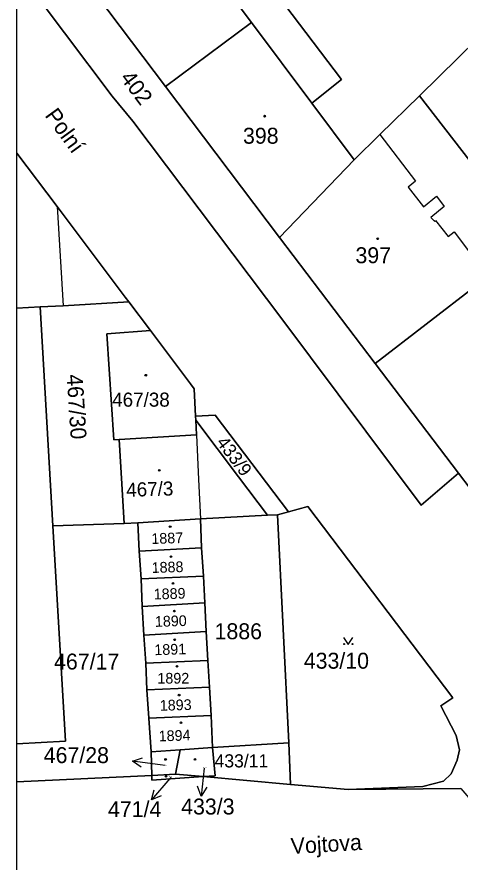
# Model space of a CAD drawing. Extents: x -598934 to -598196, y -1162208 to -1161502.
# Drawn here: x -598932 to -598884.8, y -1162016.6 to -1161926.4 of the extents above; entities that cross this region are included whole.
import ezdxf

# ---------------------------------------------------------------- set-up
doc = ezdxf.new("R2010")
doc.units = 0
for name, color, linetype in [('KN_CAR_KR', 7, 'Continuous'), ('KN_KULTURY', 7, 'Continuous'), ('KN_PARC_CIS_POM', 7, 'Continuous'), ('KN_PARC_CIS_POZ', 7, 'Continuous'), ('KN_PARC_CIS_STAV', 7, 'Continuous'), ('KN_PARC_PLOCHA', 7, 'Continuous'), ('KN_ULICE', 7, 'Continuous'), ('PARC_C_SIPKA', 7, 'Continuous'), ('parcely_l', 7, 'Continuous')]:
    doc.layers.add(name, color=color, linetype=linetype)

msp = doc.modelspace()

# ---------------------------------------------------------------- linework, layer by layer
at = {"layer": 'KN_CAR_KR'}
for points in [[(-598893.33, -1161938.99), (-598889.53, -1161943.97)], [(-598889.53, -1161943.97), (-598890.3, -1161944.59)], [(-598890.3, -1161944.59), (-598888.69, -1161946.7)], [(-598888.69, -1161946.7), (-598887.3, -1161945.55)], [(-598887.3, -1161945.55), (-598886.49, -1161946.67)], [(-598927.74, -1161946.65), (-598927.08, -1161957.24)], [(-598886.49, -1161946.67), (-598887.89, -1161947.84)], [(-598887.89, -1161947.84), (-598887.48, -1161948.25)], [(-598887.48, -1161948.25), (-598887.4, -1161948.17)], [(-598887.4, -1161948.17), (-598886.03, -1161949.88)], [(-598886.03, -1161949.88), (-598885.42, -1161949.38)], [(-598885.42, -1161949.38), (-598881.85, -1161954.09)], [(-598912.89, -1161971.03), (-598912.66, -1161975.76)], [(-598912.66, -1161975.76), (-598912.45, -1161979.98)]]:
    msp.add_lwpolyline(points, dxfattribs=at)
at = {"layer": 'KN_KULTURY'}
msp.add_lwpolyline([(-598897.192, -1161992.622), (-598896.692, -1161993.372), (-598896.192, -1161992.622)], dxfattribs=at)
for centre, radius in [((-598905.61, -1161937.03), 0.09), ((-598905.61, -1161937.03), 0.0398), ((-598893.56, -1161950.11), 0.09), ((-598893.56, -1161950.11), 0.0398), ((-598918.28, -1161964.66), 0.09), ((-598918.28, -1161964.66), 0.0398), ((-598916.84, -1161974.8), 0.09), ((-598916.84, -1161974.8), 0.0398), ((-598915.68, -1161980.81), 0.09), ((-598915.68, -1161980.81), 0.0398), ((-598915.59, -1161984), 0.09), ((-598915.59, -1161984), 0.0398), ((-598915.38, -1161986.86), 0.09), ((-598915.38, -1161986.86), 0.0398), ((-598915.23, -1161989.81), 0.09), ((-598915.23, -1161989.81), 0.0398), ((-598915.2, -1161992.87), 0.09), ((-598915.2, -1161992.87), 0.0398), ((-598897.142, -1161993.321), 0.05), ((-598896.243, -1161993.321), 0.05), ((-598914.95, -1161995.7), 0.09), ((-598914.95, -1161995.7), 0.0398), ((-598914.72, -1161998.77), 0.09), ((-598914.72, -1161998.77), 0.0398), ((-598914.53, -1162001.72), 0.09), ((-598914.53, -1162001.72), 0.0398), ((-598916.17, -1162005.63), 0.09), ((-598916.17, -1162005.63), 0.0398), ((-598913.04, -1162005.63), 0.09), ((-598913.04, -1162005.63), 0.0398), ((-598916.13, -1162007.43), 0.09), ((-598916.13, -1162007.43), 0.0398)]:
    msp.add_circle(centre, radius, dxfattribs=at)
at = {"layer": 'KN_PARC_PLOCHA'}
for points in [[(-598820.93, -1161992.32), (-598829.17, -1161992.77), (-598829.29, -1161990.1), (-598829.45, -1161986.79), (-598829.55, -1161985.5), (-598829.92, -1161978.95), (-598842.8, -1161965.85), (-598849.62, -1161958.8), (-598867.42, -1161940.58), (-598880.89, -1161926.8), (-598889.11, -1161934.86), (-598893.33, -1161938.99), (-598896.07, -1161941.68), (-598900.57, -1161935.66), (-598897.41, -1161933.11), (-598907.94, -1161919.22), (-598928.61, -1161891.58), (-598931.22, -1161882.34), (-598932.017, -1161880.677), (-598932.017, -1161860.81)], [(-598884.71, -1162008.72), (-598896.69, -1162008.84), (-598888.76, -1162008.53), (-598886.53, -1162007.94), (-598885.74, -1162007.17), (-598885.1, -1162005.69), (-598884.84, -1162004.62), (-598885.2, -1162003.07), (-598886.83, -1161999.9), (-598885.54, -1161999.06), (-598901.01, -1161978.64), (-598903.08, -1161979.22), (-598910.89, -1161968.92), (-598912.98, -1161969.02), (-598913.12, -1161966.09), (-598913.51, -1161965.57), (-598917.78, -1161959.89), (-598920.08, -1161956.84), (-598920.47, -1161956.32), (-598927.74, -1161946.65), (-598932.017, -1161940.968), (-598932.017, -1161921.366), (-598921.86, -1161934.91), (-598919.65, -1161937.58), (-598903.67, -1161958.78), (-598888.91, -1161978.52), (-598884.94, -1161975.11), (-598873.75, -1161989.83)]]:
    msp.add_lwpolyline(points, dxfattribs=at)
for points in [[(-598897.41, -1161933.11), (-598900.57, -1161935.66), (-598907.01, -1161927.05), (-598918.02, -1161912.34), (-598928.99, -1161897.67), (-598932.017, -1161893.629), (-598932.017, -1161880.677), (-598931.22, -1161882.34), (-598928.61, -1161891.58), (-598907.94, -1161919.22)], [(-598907.01, -1161927.05), (-598916.16, -1161933.87), (-598927.15, -1161919.28), (-598918.02, -1161912.34)], [(-598927.15, -1161919.28), (-598916.16, -1161933.87), (-598904.02, -1161949.98), (-598893.84, -1161963.41), (-598884.94, -1161975.11), (-598888.91, -1161978.52), (-598903.67, -1161958.78), (-598919.65, -1161937.58), (-598921.86, -1161934.91), (-598932.017, -1161921.366), (-598932.017, -1161912.818)], [(-598867.42, -1161940.58), (-598872.02, -1161944.33), (-598877.53, -1161949.83), (-598889.11, -1161934.86), (-598880.89, -1161926.8)], [(-598900.57, -1161935.66), (-598896.07, -1161941.68), (-598904.02, -1161949.98), (-598916.16, -1161933.87), (-598907.01, -1161927.05)], [(-598877.53, -1161949.83), (-598881.85, -1161954.09), (-598882.96, -1161955.02), (-598893.84, -1161963.41), (-598904.02, -1161949.98), (-598896.07, -1161941.68), (-598893.33, -1161938.99), (-598889.11, -1161934.86)], [(-598920.08, -1161956.84), (-598927.08, -1161957.24), (-598929.55, -1161957.38), (-598932.017, -1161957.521), (-598932.017, -1161940.968), (-598927.74, -1161946.65), (-598920.47, -1161956.32)], [(-598863.18, -1161981.51), (-598864.24, -1161982.22), (-598873.75, -1161989.83), (-598884.94, -1161975.11), (-598893.84, -1161963.41), (-598882.96, -1161955.02)], [(-598928.18, -1161980.72), (-598926.84, -1162003.67), (-598932.017, -1162003.962), (-598932.017, -1161957.521), (-598929.55, -1161957.38)], [(-598917.78, -1161959.89), (-598922.44, -1161960.25), (-598921.67, -1161971.54), (-598921.13, -1161971.51), (-598920.82, -1161976.25), (-598920.57, -1161980.46), (-598928.18, -1161980.72), (-598929.55, -1161957.38), (-598927.08, -1161957.24), (-598920.08, -1161956.84)], [(-598912.98, -1161969.02), (-598912.96, -1161969.44), (-598912.89, -1161971.03), (-598921.13, -1161971.51), (-598921.67, -1161971.54), (-598922.44, -1161960.25), (-598917.78, -1161959.89), (-598913.51, -1161965.57), (-598913.12, -1161966.09)], [(-598903.08, -1161979.22), (-598904.23, -1161979.56), (-598905.31, -1161979.57), (-598908.38, -1161975.5), (-598912.96, -1161969.44), (-598912.98, -1161969.02), (-598910.89, -1161968.92)], [(-598905.31, -1161979.57), (-598912.45, -1161979.98), (-598919.13, -1161980.41), (-598920.57, -1161980.46), (-598920.82, -1161976.25), (-598921.13, -1161971.51), (-598912.89, -1161971.03), (-598912.96, -1161969.44), (-598908.38, -1161975.5)], [(-598896.69, -1162008.84), (-598902.86, -1162008.29), (-598903.02, -1162003.84), (-598904.23, -1161979.56), (-598903.08, -1161979.22), (-598901.01, -1161978.64), (-598885.54, -1161999.06), (-598886.83, -1161999.9), (-598885.2, -1162003.07), (-598884.84, -1162004.62), (-598885.1, -1162005.69), (-598885.74, -1162007.17), (-598886.53, -1162007.94), (-598888.76, -1162008.53)], [(-598912.34, -1161983.07), (-598918.99, -1161983.43), (-598919.13, -1161980.41), (-598912.45, -1161979.98)], [(-598903.02, -1162003.84), (-598911.16, -1162004.34), (-598911.3, -1162000.94), (-598911.5, -1161997.93), (-598911.67, -1161995.07), (-598911.85, -1161992), (-598912, -1161988.93), (-598912.14, -1161986.1), (-598912.34, -1161983.07), (-598912.45, -1161979.98), (-598905.31, -1161979.57), (-598904.23, -1161979.56)], [(-598918.99, -1161983.43), (-598918.78, -1161986.38), (-598918.66, -1161989.31), (-598918.48, -1161992.38), (-598918.28, -1161995.35), (-598918.15, -1161998.21), (-598917.95, -1162001.21), (-598917.72, -1162004.81), (-598917.65, -1162007.34), (-598932.017, -1162008.017), (-598932.017, -1162003.962), (-598926.84, -1162003.67), (-598928.18, -1161980.72), (-598920.57, -1161980.46), (-598919.13, -1161980.41)], [(-598912.14, -1161986.1), (-598918.78, -1161986.38), (-598918.99, -1161983.43), (-598912.34, -1161983.07)], [(-598912, -1161988.93), (-598918.66, -1161989.31), (-598918.78, -1161986.38), (-598912.14, -1161986.1)], [(-598911.85, -1161992), (-598918.48, -1161992.38), (-598918.66, -1161989.31), (-598912, -1161988.93)], [(-598911.67, -1161995.07), (-598918.28, -1161995.35), (-598918.48, -1161992.38), (-598911.85, -1161992)], [(-598911.5, -1161997.93), (-598918.15, -1161998.21), (-598918.28, -1161995.35), (-598911.67, -1161995.07)], [(-598911.3, -1162000.94), (-598917.95, -1162001.21), (-598918.15, -1161998.21), (-598911.5, -1161997.93)], [(-598911.16, -1162004.34), (-598914.62, -1162004.59), (-598917.72, -1162004.81), (-598917.95, -1162001.21), (-598911.3, -1162000.94)], [(-598912.15, -1162007.46), (-598915.12, -1162007.2), (-598914.62, -1162004.59), (-598911.16, -1162004.34), (-598910.88, -1162007.38)], [(-598902.86, -1162008.29), (-598912.15, -1162007.46), (-598910.88, -1162007.38), (-598911.16, -1162004.34), (-598903.02, -1162003.84)], [(-598915.12, -1162007.2), (-598917.65, -1162007.34), (-598917.72, -1162004.81), (-598914.62, -1162004.59)], [(-598912.15, -1162007.46), (-598902.86, -1162008.29), (-598896.69, -1162008.84), (-598884.71, -1162008.72), (-598876.32, -1162018.53), (-598873.13, -1162022.24), (-598891.39, -1162023.04), (-598909.46, -1162023.88), (-598914.65, -1162024.03), (-598932.017, -1162024.888), (-598932.017, -1162008.017), (-598917.65, -1162007.34), (-598917.64, -1162007.83)], [(-598912.15, -1162007.46), (-598917.64, -1162007.83), (-598917.65, -1162007.34), (-598915.12, -1162007.2)]]:
    msp.add_lwpolyline(points, close=True, dxfattribs=at)
at = {"layer": 'PARC_C_SIPKA'}
for points in [[(-598918.779, -1162006.444), (-598919.702, -1162005.813), (-598918.644, -1162005.453)], [(-598916.2, -1162006.29), (-598916.73, -1162006.22), (-598919.702, -1162005.813)], [(-598912.06, -1162006.55), (-598912.372, -1162009.534)], [(-598915.58, -1162007.51), (-598915.71, -1162007.67), (-598917.67, -1162009.941)], [(-598916.638, -1162009.511), (-598917.67, -1162009.941), (-598917.395, -1162008.857)], [(-598911.771, -1162008.591), (-598912.372, -1162009.534), (-598912.765, -1162008.487)]]:
    msp.add_lwpolyline(points, dxfattribs=at)
at = {"layer": 'parcely_l'}
for points in [[(-598897.41, -1161933.11), (-598907.94, -1161919.22), (-598928.61, -1161891.58), (-598931.22, -1161882.34), (-598932.017, -1161880.677)], [(-598918.02, -1161912.34), (-598907.01, -1161927.05)], [(-598916.16, -1161933.87), (-598927.15, -1161919.28)], [(-598884.94, -1161975.11), (-598888.91, -1161978.52), (-598903.67, -1161958.78), (-598919.65, -1161937.58), (-598921.86, -1161934.91), (-598932.017, -1161921.366)], [(-598932.017, -1161940.968), (-598932.017, -1161921.366)], [(-598889.11, -1161934.86), (-598880.89, -1161926.8), (-598867.42, -1161940.58)], [(-598907.01, -1161927.05), (-598916.16, -1161933.87)], [(-598907.01, -1161927.05), (-598900.57, -1161935.66)], [(-598900.57, -1161935.66), (-598897.41, -1161933.11)], [(-598916.16, -1161933.87), (-598904.02, -1161949.98)], [(-598889.11, -1161934.86), (-598893.33, -1161938.99), (-598896.07, -1161941.68)], [(-598877.53, -1161949.83), (-598889.11, -1161934.86)], [(-598900.57, -1161935.66), (-598896.07, -1161941.68)], [(-598920.08, -1161956.84), (-598920.47, -1161956.32), (-598927.74, -1161946.65), (-598932.017, -1161940.968)], [(-598932.017, -1161957.521), (-598932.017, -1161940.968)], [(-598896.07, -1161941.68), (-598904.02, -1161949.98)], [(-598904.02, -1161949.98), (-598893.84, -1161963.41)], [(-598882.96, -1161955.02), (-598893.84, -1161963.41)], [(-598932.017, -1161957.521), (-598929.55, -1161957.38)], [(-598929.55, -1161957.38), (-598927.08, -1161957.24), (-598920.08, -1161956.84)], [(-598929.55, -1161957.38), (-598928.18, -1161980.72)], [(-598920.08, -1161956.84), (-598917.78, -1161959.89)], [(-598932.017, -1162003.962), (-598932.017, -1161957.521)], [(-598921.13, -1161971.51), (-598921.67, -1161971.54), (-598922.44, -1161960.25), (-598917.78, -1161959.89)], [(-598917.78, -1161959.89), (-598913.51, -1161965.57), (-598913.12, -1161966.09), (-598912.98, -1161969.02)], [(-598893.84, -1161963.41), (-598884.94, -1161975.11)], [(-598912.98, -1161969.02), (-598910.89, -1161968.92), (-598903.08, -1161979.22)], [(-598912.96, -1161969.44), (-598912.98, -1161969.02)], [(-598921.13, -1161971.51), (-598912.89, -1161971.03), (-598912.96, -1161969.44)], [(-598912.96, -1161969.44), (-598908.38, -1161975.5), (-598905.31, -1161979.57)], [(-598920.57, -1161980.46), (-598920.82, -1161976.25), (-598921.13, -1161971.51)], [(-598873.75, -1161989.83), (-598884.94, -1161975.11)], [(-598903.08, -1161979.22), (-598901.01, -1161978.64), (-598885.54, -1161999.06), (-598886.83, -1161999.9), (-598885.2, -1162003.07), (-598884.84, -1162004.62), (-598885.1, -1162005.69), (-598885.74, -1162007.17), (-598886.53, -1162007.94), (-598888.76, -1162008.53), (-598896.69, -1162008.84)], [(-598912.45, -1161979.98), (-598919.13, -1161980.41)], [(-598905.31, -1161979.57), (-598912.45, -1161979.98)], [(-598912.34, -1161983.07), (-598912.45, -1161979.98)], [(-598905.31, -1161979.57), (-598904.23, -1161979.56)], [(-598904.23, -1161979.56), (-598903.08, -1161979.22)], [(-598903.02, -1162003.84), (-598904.23, -1161979.56)], [(-598928.18, -1161980.72), (-598926.84, -1162003.67), (-598932.017, -1162003.962)], [(-598920.57, -1161980.46), (-598928.18, -1161980.72)], [(-598919.13, -1161980.41), (-598920.57, -1161980.46)], [(-598918.99, -1161983.43), (-598919.13, -1161980.41)], [(-598912.34, -1161983.07), (-598918.99, -1161983.43)], [(-598918.78, -1161986.38), (-598918.99, -1161983.43)], [(-598912.14, -1161986.1), (-598912.34, -1161983.07)], [(-598918.78, -1161986.38), (-598912.14, -1161986.1)], [(-598912, -1161988.93), (-598912.14, -1161986.1)], [(-598918.66, -1161989.31), (-598918.78, -1161986.38)], [(-598912, -1161988.93), (-598918.66, -1161989.31)], [(-598911.85, -1161992), (-598912, -1161988.93)], [(-598918.48, -1161992.38), (-598918.66, -1161989.31)], [(-598918.48, -1161992.38), (-598911.85, -1161992)], [(-598918.28, -1161995.35), (-598918.48, -1161992.38)], [(-598911.85, -1161992), (-598911.67, -1161995.07)], [(-598911.67, -1161995.07), (-598918.28, -1161995.35)], [(-598911.5, -1161997.93), (-598911.67, -1161995.07)], [(-598918.15, -1161998.21), (-598918.28, -1161995.35)], [(-598918.15, -1161998.21), (-598911.5, -1161997.93)], [(-598911.3, -1162000.94), (-598911.5, -1161997.93)], [(-598917.95, -1162001.21), (-598918.15, -1161998.21)], [(-598917.95, -1162001.21), (-598911.3, -1162000.94)], [(-598917.72, -1162004.81), (-598917.95, -1162001.21)], [(-598911.3, -1162000.94), (-598911.16, -1162004.34)], [(-598932.017, -1162008.017), (-598932.017, -1162003.962)], [(-598911.16, -1162004.34), (-598914.62, -1162004.59)], [(-598912.15, -1162007.46), (-598910.88, -1162007.38), (-598911.16, -1162004.34)], [(-598911.16, -1162004.34), (-598903.02, -1162003.84)], [(-598903.02, -1162003.84), (-598902.86, -1162008.29)], [(-598914.62, -1162004.59), (-598917.72, -1162004.81)], [(-598917.65, -1162007.34), (-598917.72, -1162004.81)], [(-598914.62, -1162004.59), (-598915.12, -1162007.2)], [(-598932.017, -1162008.017), (-598917.65, -1162007.34)], [(-598915.12, -1162007.2), (-598917.65, -1162007.34)], [(-598912.15, -1162007.46), (-598917.64, -1162007.83), (-598917.65, -1162007.34)], [(-598915.12, -1162007.2), (-598912.15, -1162007.46)], [(-598902.86, -1162008.29), (-598912.15, -1162007.46)], [(-598932.017, -1162024.888), (-598932.017, -1162008.017)], [(-598896.69, -1162008.84), (-598902.86, -1162008.29)], [(-598896.69, -1162008.84), (-598884.71, -1162008.72)]]:
    msp.add_lwpolyline(points, dxfattribs=at)

# ---------------------------------------------------------------- texts
at = {"layer": 'KN_PARC_CIS_POM'}
for s, p in [('467/28', (-598916.483, -1162006.29)), ('433/3', (-598912.143, -1162006.55)), ('471/4', (-598915.813, -1162007.51))]:
    msp.add_text(s, height=0.1, dxfattribs=at).set_placement(p)
at = {"layer": 'KN_PARC_CIS_POZ'}
for s, height, rotation, p in [('402', 1.7, 306.89866, (-598921.081, -1161932.977)), ('467/30', 1.7, 273.5996, (-598926.712, -1161964.603)), ('433/9', 1.4, 307.29291, (-598910.819, -1161971.841))]:
    msp.add_text(s, height=height, rotation=rotation, dxfattribs=at).set_placement(p)
for s, height, p in [('1886', 1.7, (-598910.947, -1161992.81)), ('467/17', 1.7, (-598928.057, -1161996.04)), ('433/10', 1.7, (-598901.437, -1161995.95)), ('433/11', 1.4, (-598910.947, -1162006.48))]:
    msp.add_text(s, height=height, dxfattribs=at).set_placement(p)
at = {"layer": 'KN_PARC_CIS_STAV'}
for s, height, p in [('398', 1.7, (-598907.917, -1161939.97)), ('397', 1.7, (-598895.927, -1161952.71)), ('467/38', 1.5, (-598921.86, -1161968.01)), ('1892', 1.14, (-598917.04, -1161997.54)), ('467/28', 1.7, (-598929.157, -1162006.02)), ('433/3', 1.7, (-598914.507, -1162011.5)), ('471/4', 1.7, (-598922.307, -1162011.78))]:
    msp.add_text(s, height=height, dxfattribs=at).set_placement(p)
for s, height, rotation, p in [('467/3', 1.5, 1.80065, (-598920.338, -1161977.63)), ('1887', 1.14, 1.80159, (-598917.669, -1161982.656)), ('1888', 1.14, 1.80159, (-598917.639, -1161985.746)), ('1889', 1.14, 1.80159, (-598917.419, -1161988.576)), ('1890', 1.14, 1.80159, (-598917.289, -1161991.496)), ('1891', 1.14, 1.80159, (-598917.349, -1161994.516)), ('1893', 1.14, 1.80159, (-598916.769, -1162000.446)), ('1894', 1.14, 1.80159, (-598916.889, -1162003.706))]:
    msp.add_text(s, height=height, rotation=rotation, dxfattribs=at).set_placement(p)
at = {"layer": 'KN_ULICE'}
for s, rotation, p in [('Polní', 306.00031, (-598929.102, -1161936.96)), ('Vojtova', 3.39926, (-598902.776, -1162015.724))]:
    msp.add_text(s, height=1.7, rotation=rotation, dxfattribs=at).set_placement(p)

doc.saveas('drawing.dxf')
